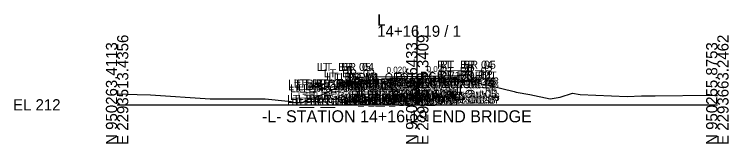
# Model space of a CAD drawing. Extents: x -26 to 7053, y -10 to 7035.
# Drawn here: x 2274.3 to 2452.8, y -9.7 to 22.6 of the extents above; entities that cross this region are included whole.
import ezdxf

# ---------------------------------------------------------------- set-up
doc = ezdxf.new("R2010")
doc.units = 0
for name, color, linetype in [('Default', 7, 'Continuous'), ('Exist Cross Section Cell', 7, 'Continuous'), ('Exist XS Center Line Elevation Label', 7, 'Continuous'), ('Exist XS Ground Line', 7, 'Continuous'), ('Prop CMT Concrete Structures', 7, 'Continuous'), ('Prop XS SE Text', 7, 'Continuous'), ('Prop XSC Text', 7, 'Continuous')]:
    doc.layers.add(name, color=color, linetype=linetype)

msp = doc.modelspace()

# ---------------------------------------------------------------- linework, layer by layer
at = {"layer": 'Exist Cross Section Cell'}
for p, q in [((2375, 0), (2375, 19.76)), ((2300, 0), (2375, 0)), ((2375, 0), (2450, 0))]:
    msp.add_line(p, q, dxfattribs=at)
at = {"layer": 'Exist XS Ground Line'}
for p, q in [((2351.78, 2.7), (2357.3, 5.49)), ((2357.3, 5.49), (2358.3, 5.63)), ((2358.3, 5.63), (2366.93, 6.45)), ((2366.93, 6.45), (2367.34, 6.47)), ((2367.34, 6.47), (2367.74, 6.48)), ((2367.74, 6.48), (2375, 6.58)), ((2375, 6.58), (2375.37, 6.59)), ((2375.37, 6.59), (2382.32, 6.45)), ((2382.32, 6.45), (2383.06, 6.44)), ((2383.06, 6.44), (2387.48, 6.04)), ((2387.48, 6.04), (2393.37, 4.75)), ((2393.37, 4.75), (2399.19, 3.32)), ((2300, 2.71), (2305.03, 2.54)), ((2305.03, 2.54), (2308.36, 2.52)), ((2308.36, 2.52), (2323.24, 1.48)), ((2348.04, 1.46), (2349.52, 1.9)), ((2349.52, 1.9), (2351.78, 2.7)), ((2399.19, 3.32), (2399.74, 3.18)), ((2399.74, 3.18), (2403.17, 2.6)), ((2403.17, 2.6), (2408.23, 1.47)), ((2408.23, 1.47), (2410.68, 1.9)), ((2410.68, 1.9), (2413.81, 2.87)), ((2413.81, 2.87), (2415.74, 2.56)), ((2415.74, 2.56), (2427.49, 2.09)), ((2427.49, 2.09), (2431.02, 2.26)), ((2431.02, 2.26), (2432.8, 2.22)), ((2432.8, 2.22), (2434.43, 2.23)), ((2434.43, 2.23), (2448.21, 2.4)), ((2448.21, 2.4), (2448.81, 2.39)), ((2448.81, 2.39), (2449.36, 2.35)), ((2449.36, 2.35), (2450, 2.35)), ((2323.24, 1.48), (2325.32, 1.51)), ((2325.32, 1.51), (2333.56, 1.47)), ((2333.56, 1.47), (2337.02, 1.47)), ((2337.02, 1.47), (2342.75, 0.9)), ((2342.75, 0.9), (2343.44, 0.8)), ((2343.44, 0.8), (2344.29, 0.54)), ((2344.29, 0.54), (2346.31, 0.58)), ((2346.31, 0.58), (2348.04, 1.46))]:
    msp.add_line(p, q, dxfattribs=at)
at = {"layer": 'Prop CMT Concrete Structures'}
for points in [[(2375, 7.09), (2365, 6.89), (2359.17, 6.78), (2359.16, 7.03), (2358.58, 7.86), (2358.41, 9.44), (2357.67, 9.44), (2357.67, 5.25)], [(2375, 7.09), (2385, 7.29), (2387, 7.33), (2387.01, 7.58), (2387.59, 8.42), (2387.76, 10), (2388.5, 10), (2388.5, 5.86)], [(2357.67, 5.25), (2365, 5.39), (2375, 5.59)], [(2375, 5.59), (2374.17, 5.58)], [(2374.17, 5.58), (2374.17, 4.93)], [(2375, 5.59), (2375, 7.09)], [(2375, 5.59), (2375, 7.09)], [(2388.5, 5.86), (2385, 5.79), (2375, 5.59)], [(2375, 5.59), (2375.83, 5.61)], [(2375, 1.09), (2375, 5.59)], [(2375, 1.09), (2375, 5.59)], [(2375.83, 5.61), (2375.83, 4.93)], [(2384.54, 5.79), (2385.38, 5.8), (2386.21, 5.82)], [(2384.54, 5.14), (2384.54, 5.79)], [(2386.21, 5.82), (2386.21, 5.14)], [(2361.63, 5.33), (2360.79, 5.31), (2359.96, 5.29)], [(2359.96, 5.29), (2359.96, 4.64)], [(2359.96, 4.64), (2360.46, 4.14)], [(2360.46, 4.14), (2360.46, 2.23)], [(2361.13, 4.14), (2361.63, 4.64)], [(2361.13, 2.23), (2361.13, 4.14)], [(2361.63, 4.64), (2361.63, 5.33)], [(2374.17, 4.93), (2374.67, 4.43)], [(2374.67, 4.43), (2374.67, 2.51)], [(2375.83, 4.93), (2375.33, 4.43)], [(2375.33, 4.43), (2375.33, 2.51)], [(2385.04, 4.64), (2384.54, 5.14)], [(2385.04, 2.72), (2385.04, 4.64)], [(2386.21, 5.14), (2385.71, 4.64)], [(2385.71, 4.64), (2385.71, 2.72)], [(2360.46, 2.23), (2359.71, 1.48)], [(2361.88, 1.48), (2361.13, 2.23)], [(2374.67, 2.51), (2373.92, 1.76)], [(2375.33, 2.51), (2376.08, 1.76)], [(2384.29, 1.97), (2385.04, 2.72)], [(2384.29, 1.3), (2384.29, 1.97)], [(2385.71, 2.72), (2386.46, 1.97)], [(2386.46, 1.97), (2386.46, 1.3)], [(2359.71, 1.48), (2359.71, 0.81)], [(2359.71, 0.81), (2360.79, 0.81), (2361.88, 0.81)], [(2361.88, 0.81), (2361.88, 1.48)], [(2373.92, 1.76), (2373.92, 1.09)], [(2373.92, 1.09), (2375, 1.09)], [(2376.08, 1.09), (2375, 1.09)], [(2376.08, 1.76), (2376.08, 1.09)], [(2386.46, 1.3), (2385.38, 1.3), (2384.29, 1.3)]]:
    msp.add_lwpolyline(points, dxfattribs=at)

# ---------------------------------------------------------------- texts
at = {"layer": 'Default'}
for s, height, p in [('RT_ BR_04', 2, (2379.95, 9)), ('RT_ BR_05', 2, (2380.69, 9)), ('LT_ BR_05', 2, (2349.91, 8.44)), ('LT_ BR_04', 2, (2350.65, 8.44)), ('RT_BR_03', 2, (2380.6, 7.42)), ('LT_BR_03', 2, (2351.63, 6.86)), ('LT_BR_02', 2, (2352.22, 6.03)), ('LT_BR_01', 2, (2352.79, 5.78)), ('LT_PV1_OEOT', 2, (2355.74, 5.89)), ('PV1_PGL', 2, (2369.47, 6.09)), ('RT_PV1_OEOT', 2, (2375.69, 6.29)), ('RT_BR_02', 2, (2380.02, 6.58)), ('RT_BR_01', 2, (2380.57, 6.33)), ('LT_BR_Girder Out 02', 2, (2342.75, 4.29)), ('LT_BR_Girder Out 03', 2, (2342.75, 3.64)), ('LT_BR_Girder Out 01', 2, (2344.15, 4.31)), ('LT_BR_Girder Out 14', 2, (2345.06, 4.33)), ('LT_BR_Girder Out 13', 2, (2345.06, 3.64)), ('LT_BR_06', 2, (2350.68, 4.25)), ('LT_BR_Girder Mid 02', 2, (2357.35, 4.58)), ('LT_BR_Girder Mid 03', 2, (2357.35, 3.93)), ('LT_BR_Girder Mid 04', 2, (2357.85, 3.43)), ('LT_BR_07', 2, (2358.06, 4.39)), ('RT_BR_Girder Mid 04', 2, (2358.47, 3.43)), ('RT_BR_Girder Mid 02', 2, (2358.97, 4.61)), ('RT_BR_Girder Mid 03', 2, (2358.97, 3.93)), ('RT_BR_Girder Out 14', 2, (2367.93, 4.79)), ('RT_BR_Girder Out 13', 2, (2367.93, 4.14)), ('RT_BR_Girder Out 12', 2, (2368.43, 3.64)), ('RT_BR_Girder Out 04', 2, (2368.45, 3.64)), ('RT_BR_Girder Out 01', 2, (2368.68, 4.8)), ('RT_BR_Girder Out 02', 2, (2368.95, 4.82)), ('RT_BR_Girder Out 03', 2, (2368.95, 4.14)), ('BR_PGL', 2, (2369.83, 4.59)), ('RT_BR_07', 2, (2378.01, 4.79)), ('RT_BR_06', 2, (2381.46, 4.86)), ('LT_BR_Girder Out 04', 2, (2343.25, 3.14)), ('LT_BR_Girder Out 12', 2, (2344.56, 3.14)), ('LT_BR_Girder Mid 05', 2, (2357.85, 1.51)), ('RT_BR_Girder Mid 05', 2, (2358.47, 1.51)), ('RT_BR_Girder Out 05', 2, (2368.45, 1.72)), ('RT_BR_Girder Out 11', 2, (2369, 1.72)), ('LT_BR_Girder Out 06', 2, (2342.45, 0.48)), ('LT_BR_Girder Out 07', 2, (2342.5, -0.19)), ('LT_BR_Girder Out 05', 2, (2343.25, 1.23)), ('LT_BR_Girder Out 08', 2, (2343.58, -0.19)), ('LT_BR_Girder Out 09', 2, (2344.66, -0.19)), ('LT_BR_Girder Out 11', 2, (2345.13, 1.23)), ('LT_BR_Girder Out 10', 2, (2345.23, 0.48)), ('LT_BR_Girder Mid 06', 2, (2357.05, 0.76)), ('LT_BR_Girder Mid 07', 2, (2357.1, 0.09)), ('RT_BR_Girder Mid 06', 2, (2359.17, 0.76)), ('RT_BR_Girder Mid 07', 2, (2359.22, 0.09)), ('BR_Girder Mid 08', 2, (2360.87, 0.09)), ('RT_BR_Girder Out 09', 2, (2367.03, 0.3)), ('RT_BR_Girder Out 10', 2, (2367.6, 0.97)), ('RT_BR_Girder Out 08', 2, (2368.12, 0.3)), ('RT_BR_Girder Out 06', 2, (2369.15, 0.97)), ('RT_BR_Girder Out 07', 2, (2369.2, 0.3)), ('-', 0.0001, (2300, 0))]:
    msp.add_text(s, height=height, dxfattribs=at).set_placement(p)
at = {"layer": 'Exist Cross Section Cell'}
for s, p in [('L', (2365, 19.76)), ('14+16.19 / 1', (2365, 16.96)), ('EL 212', (2274, -1.4))]:
    msp.add_text(s, height=2.8, dxfattribs=at).set_placement(p)
for s, p in [('E 2293513.4356', (2302.8, -10)), ('E 2293588.3409', (2377.8, -10)), ('E 2293663.2462', (2452.8, -10)), ('N 950263.4113', (2300, -10)), ('N 950259.6433', (2375, -10)), ('N 950255.8753', (2450, -10))]:
    msp.add_text(s, height=2.8, rotation=90, dxfattribs=at).set_placement(p)
at = {"layer": 'Exist XS Center Line Elevation Label'}
msp.add_text('218.58', height=2, dxfattribs=at).set_placement((2370.96, 1.58))
at = {"layer": 'Prop XS SE Text'}
for p in [(2367.36, 7.94), (2377.36, 8.14)]:
    msp.add_text('0.020', height=1.5, rotation=1.1458, dxfattribs=at).set_placement(p)
at = {"layer": 'Prop XSC Text'}
msp.add_text('-L- STATION 14+16.19 END BRIDGE', height=3, dxfattribs=at).set_placement((2336.19, -4.37))

doc.saveas('drawing.dxf')
